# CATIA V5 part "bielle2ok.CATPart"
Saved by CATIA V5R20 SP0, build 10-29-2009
Part number: Part1
Bounding box of the stored display mesh (mm): x 0 to 19, y -5.85 to 134.85, z -3 to 9
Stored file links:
  E:\IAO_2010\iao\IAO_MMS_Groupe1\Problemes\tlampure\tlampure\tlampure\bielle2ok.CATPart
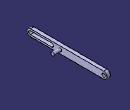
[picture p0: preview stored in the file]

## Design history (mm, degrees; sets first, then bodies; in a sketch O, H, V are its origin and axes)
Body1 (main body)
  Sketch1 on yz-plane, origin (0, 0, 0), H (0, 1, 0), V (0, 0, 1)
    point P1 (0, -3)
    line L1 (0, -3) -> (129, -3)
    arc A1 centre (129, 3) radius 6 from (129, -3) to (129, 9) ccw
    line L2 (129, 9) -> (0, 9)
    point P5 (0, 9)
    arc A2 centre (0, 3) radius 6 from (0, 9) to (0, -3) ccw
    circle A3 centre (129, 3) radius 3
    line L3 (0, 0) -> (38, 0)
    arc A4 centre (38, 3) radius 3 from (38, 0) to (38, 6) ccw
    line L4 (38, 6) -> (0, 6)
    point P10 (0, 6)
    arc A5 centre (0, 3) radius 3 from (0, 6) to (0, 0) ccw
    distance L1 L2 = 12
    distance L3 L4 = 6
    length L2 = 129
    length L4 = 38
    coincidence: P1 V, P5 V, P10 V
    horizontal: L1 H, L3 H
    tangency: A1 L1, L2 A1, A2 L1, A2 L2, A4 L3, L4 A4, A5 L3, A5 L4
    concentricity: A5 A2
  Pad1: profile Sketch1, direction (1, 0, 0), length 6
  Sketch2 on end face of Pad1, origin (6, 0, 0), H (0, 1, 0), V (0, 0, 1)
    circle A1 centre (52.3457, 3) radius 3
    reference projected line E1 (0, 0) -> (50, 0) from edge [end face of Pad1 | face of Pad1 from Sketch1.L3]
    tangency: E1 A1
  Pad2: profile Sketch2, direction (1, 0, 0), length 13
  Sketch3 on end face of Pad1, origin (6, 0, 0), H (0, 1, 0), V (0, 0, 1)
    line L1 (41, 3) -> (-3, 3)
    point P1 (41, 3)
    point P2 (-3, 3)
    reference projected arc E1 centre (38, 3) radius 3 from (38, 0) to (38, 6) ccw from edge [end face of Pad1 | face of Pad1 from Sketch1.A4]
    reference projected arc E2 centre (0, 3) radius 3 from (0, 6) to (0, 0) ccw from edge [end face of Pad1 | face of Pad1 from Sketch1.A5]
    reference projected line E3 (38, 6) -> (0, 6) from edge [end face of Pad1 | face of Pad1 from Sketch1.L4]
    distance P1 E1 = 0
    distance P2 E2 = 0
    distance L1 E3 = 3
    horizontal: L1 H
